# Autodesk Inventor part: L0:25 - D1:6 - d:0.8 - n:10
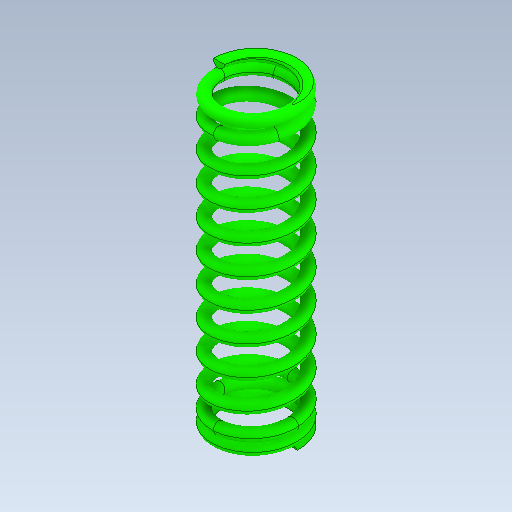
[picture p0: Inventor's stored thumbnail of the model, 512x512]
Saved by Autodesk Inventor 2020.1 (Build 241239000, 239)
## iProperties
CustomPartVersion: 1
Created: 2020-04
Part Number: L0:25 - D1:6 - d:0.8 - n:10
Material: Steel
Document SubType Name: Modeling
Designer: Safarabadi
Density: 2.18 g/cm^3
Appearance: Steel(1)
Description: Compress Spring
Author: Safarabadi
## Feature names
1. Main Coil Feature(R)
2. Start Transition Coil 1(Right)
3. Coil  Start Transition 2(R)
4. Coil  Start Transition 3(R)
5. Coil  Start Transition 4(R)
6. Start Ends Coil(Right)
7. Start Cut Feature(Right) [Extrusion]
8. End Transition Coil 1(Right)
9. End Transition Coil 2(Right)
10. End Transition Coil 3(Right)
11. End Transition Coil 4(Right)
12. End Coil(Right)
13. End Cut Feature(Right) [Extrusion]
14. Plain Ends Cut Feature 1(Right) [Extrusion]
15. Plain Ends Cut  2(R) [Extrusion]
16. Main Coil Feature(L)
17. Start Transition Coil 1(Left)
18. Start Transition Coil 2(Left)
19. Start Transition Coil 3(Left)
20. Start Transition Coil 4(Left)
21. Start Ends Coil(Left)
22. Start Cut Feature(Left) [Extrusion]
23. End Transition Coil 1(Left)
24. End Transition Coil 2(Left)
25. End Transition Coil 3(Left)
26. End Transition Coil 4(Left)
27. End Coil(Left)
28. End Cut Feature(Left) [Extrusion]
29. Cut Plain Ends Cut 1(L) [Extrusion]
30. Cut Plain Ends Cut 2(L) [Extrusion]
## Parameters: d0 = 0.2 mm, da_d = 0.8 mm, da_D2 = 4.4 mm, da_ti = 2.05736 mm, da_nz1 = 15 mm, spiral_Angle = 1.25279 mm, d2 = 2.05736 mm, d4 = 82.5 mm, d5 = 0, d6 = 90 deg, d7 = 90 deg, d8 = 0, d9 = 0, d12 = 1.75366 mm, d13 = -2.27311 mm, d14 = 0.8 mm, d15 = 0, d16 = 1.74302 mm, d18 = 2.5 mm, d19 = 0, d20 = 90 deg, d21 = 90 deg, d22 = 0, d23 = 0, d24 = 1.42868 mm, d26 = 2.5 mm, d27 = 0, d28 = 90 deg, d29 = 90 deg, d30 = 0, d31 = 0, d32 = 1.11434 mm, d34 = 2.5 mm, d35 = 0, d36 = 90 deg, d37 = 90 deg, d38 = 0, d39 = 0, d40 = 0.8 mm, d42 = 2.5 mm, d43 = 0, d44 = 90 deg, d45 = 90 deg, d46 = 0, d47 = 0, d48 = 1.74302 mm, d50 = 1.875 mm, d51 = 0, d52 = 90 deg, d53 = 90 deg, d54 = 0, d55 = 0, d56 = 1.42868 mm, d58 = 1.875 mm, d59 = 0, d60 = 90 deg, d61 = 90 deg, d62 = 0, d63 = 0, d64 = 1.11434 mm, d66 = 1.875 mm, d67 = 0, d68 = 90 deg, d69 = 90 deg, d70 = 0, d71 = 0, d72 = 0.8 mm, d74 = 1.875 mm, d75 = 0, d76 = 90 deg, d77 = 90 deg, d78 = 0, d79 = 0, End_Pitch = 0.80632 mm, d82 = 15 mm, d83 = 0, d84 = 90 deg, d85 = 90 deg, d86 = 0, d87 = 0, d88 = 0.80632 mm, d91 = 0, d92 = 90 deg, d93 = 90 deg, d94 = 0, d95 = 0, d96 = 6 mm, d97 = 0.80632 mm, d98 = 0, d99 = 6 mm, d100 = 0.80632 mm, d101 = 0, d102 = 0, d103 = 0, d104 = 0, d105 = 0, d106 = 0, d108 = 0, d112 = 0, d113 = 0, d114 = 0, const_zero = 0, Not_rightdir = 0, d121 = 0.20787 mm, d131 = 0, d132 = 0, d133 = 0, d134 = 0, d135 = 0.2 mm, d137 = 2.05736 mm, d139 = 82.5 mm, d140 = 0, d141 = 90 deg, d142 = 90 deg, d143 = 0, d144 = 0, d145 = 1.75366 mm, d146 = -2.27311 mm, d147 = 0.20787 mm, d148 = 0.00629 mm, d149 = 0.8 mm, d150 = 0, d151 = 0, d152 = 1.74302 mm, d154 = 2.5 mm, d155 = 0, d156 = 90 deg, d157 = 90 deg, d158 = 0, d159 = 0, d160 = 1.42868 mm, d162 = 2.5 mm, d163 = 0, d164 = 90 deg, d165 = 90 deg, d166 = 0, d167 = 0, d168 = 1.11434 mm, d170 = 2.5 mm, d171 = 0, d172 = 90 deg, d173 = 90 deg, d174 = 0, d175 = 0, d176 = 0.8 mm, d178 = 2.5 mm, d179 = 0, d180 = 90 deg, d181 = 90 deg, d182 = 0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
